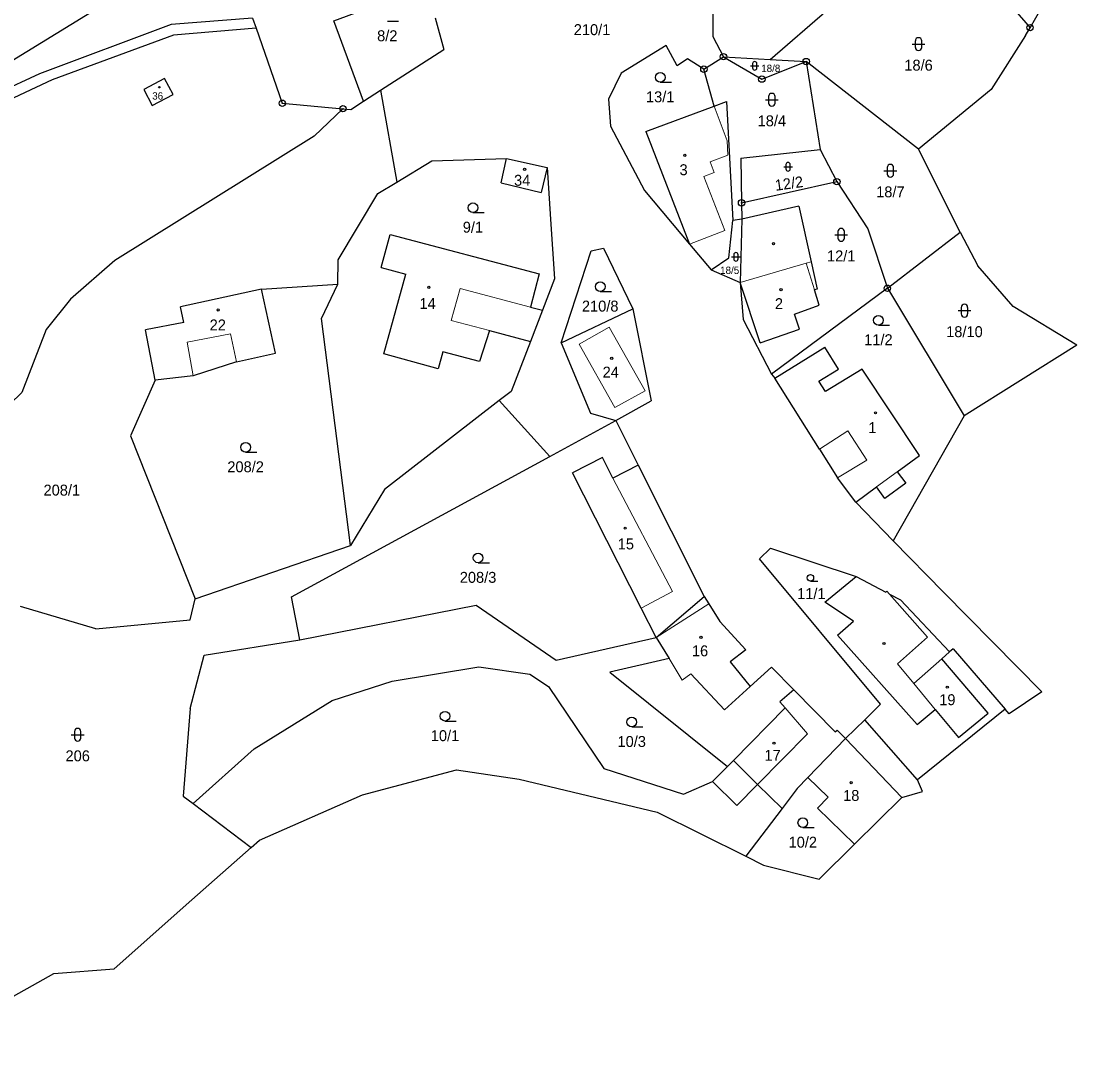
# Model space of a CAD drawing. Extents: x -601877 to -599786, y -1122905 to -1121218.
# Drawn here: x -599979.4 to -599815.2, y -1122397.6 to -1122237.3 of the extents above; entities that cross this region are included whole.
import ezdxf
from ezdxf.enums import TextEntityAlignment as Align

# ---------------------------------------------------------------- set-up
doc = ezdxf.new("R2010")
doc.units = 0
doc.header["$LTSCALE"] = 0.68
for name, color, linetype, lineweight in [('1', 7, 'Continuous', 25), ('3', 7, 'Continuous', 25), ('4', 7, 'Continuous', 13), ('5', 7, 'Continuous', 25), ('8', 7, 'Continuous', 25)]:
    doc.layers.add(name, color=color, linetype=linetype, lineweight=lineweight)
doc.layers.add('2', color=7, linetype='Continuous')

msp = doc.modelspace()

# ---------------------------------------------------------------- linework, layer by layer
at = {"layer": '1'}
for p, q in [((-599832.94, -1122226.2), (-599822.46, -1122238.34)), ((-600006.61, -1122259.26), (-599955.88, -1122228.15)), ((-599822.46, -1122238.34), (-599817.45, -1122229.46)), ((-599871.81, -1122230.28), (-599871.81, -1122239.72)), ((-599862.87, -1122243.28), (-599854, -1122235.63)), ((-599943.4, -1122236.87), (-599942.86, -1122238.42)), ((-599914.97, -1122236.8), (-599913.64, -1122241.71)), ((-599942.86, -1122238.42), (-599955.7, -1122239.53)), ((-599942.86, -1122238.42), (-599938.77, -1122250.1)), ((-599823.14, -1122239.56), (-599822.46, -1122238.34)), ((-599955.7, -1122239.53), (-599974.57, -1122246.46)), ((-599871.81, -1122239.72), (-599870.14, -1122242.85)), ((-599823.14, -1122239.56), (-599828.49, -1122247.93)), ((-599923.49, -1122248.07), (-599913.64, -1122241.71)), ((-599879.04, -1122241.11), (-599886.04, -1122245.39)), ((-599877.33, -1122244.28), (-599879.04, -1122241.11)), ((-599875.74, -1122243.19), (-599877.33, -1122244.28)), ((-599873.19, -1122244.79), (-599875.74, -1122243.19)), ((-599873.19, -1122244.79), (-599870.14, -1122242.85)), ((-599870.14, -1122242.85), (-599862.87, -1122243.28)), ((-599870.14, -1122242.85), (-599864.18, -1122246.34)), ((-599864.18, -1122246.34), (-599857.27, -1122243.61)), ((-599862.87, -1122243.28), (-599857.27, -1122243.61)), ((-599839.83, -1122257.22), (-599857.27, -1122243.61)), ((-599857.27, -1122243.61), (-599855.12, -1122257.3)), ((-599976.54, -1122245.54), (-600006.61, -1122259.26)), ((-599886.04, -1122245.39), (-599888.03, -1122249.47)), ((-599871.6, -1122250.53), (-599873.19, -1122244.79)), ((-599974.57, -1122246.46), (-600009.65, -1122262.88)), ((-599957.1, -1122246.26), (-599960.33, -1122247.96)), ((-599955.77, -1122248.75), (-599957.1, -1122246.26)), ((-599960.33, -1122247.96), (-599958.99, -1122250.44)), ((-599958.99, -1122250.44), (-599955.77, -1122248.75)), ((-599926.15, -1122249.79), (-599923.49, -1122248.07)), ((-599923.49, -1122248.07), (-599920.98, -1122262.38)), ((-599828.49, -1122247.93), (-599839.83, -1122257.22)), ((-599938.77, -1122250.1), (-599929.33, -1122250.94)), ((-599928.09, -1122251.05), (-599926.15, -1122249.79)), ((-599888.03, -1122249.47), (-599887.7, -1122253.66)), ((-599882.23, -1122254.5), (-599871.6, -1122250.53)), ((-599871.6, -1122250.53), (-599869.68, -1122249.81)), ((-599869.68, -1122249.81), (-599868.68, -1122268.34)), ((-599929.33, -1122250.94), (-599933.84, -1122255.22)), ((-599929.33, -1122250.94), (-599928.09, -1122251.05)), ((-599887.7, -1122253.66), (-599882.41, -1122263.69)), ((-599933.84, -1122255.22), (-599964.82, -1122274.55)), ((-599882.23, -1122254.5), (-599875.42, -1122272.02)), ((-599867.45, -1122258.61), (-599855.12, -1122257.3)), ((-599855.12, -1122257.3), (-599852.5, -1122262.29)), ((-599833.33, -1122270.16), (-599839.83, -1122257.22)), ((-599920.98, -1122262.38), (-599915.49, -1122259.04)), ((-599915.49, -1122259.04), (-599903.9, -1122258.67)), ((-599904.75, -1122262.46), (-599903.9, -1122258.67)), ((-599903.9, -1122258.67), (-599897.58, -1122260.09)), ((-599867.45, -1122258.61), (-599867.33, -1122265.58)), ((-599897.58, -1122260.09), (-599898.52, -1122263.97)), ((-599897.58, -1122260.09), (-599897.06, -1122268.12)), ((-599923.9, -1122264.15), (-599920.98, -1122262.38)), ((-599867.33, -1122265.58), (-599852.5, -1122262.29)), ((-599852.5, -1122262.29), (-599847.69, -1122269.61)), ((-599904.75, -1122262.46), (-599898.52, -1122263.97)), ((-599882.41, -1122263.69), (-599875.42, -1122272.02)), ((-599930.06, -1122274.45), (-599923.9, -1122264.15)), ((-599867.33, -1122265.58), (-599867.28, -1122268.11)), ((-599858.4, -1122266.12), (-599867.28, -1122268.11)), ((-599858.4, -1122266.12), (-599856.5, -1122274.74)), ((-599897.06, -1122268.12), (-599896.41, -1122277.42)), ((-599869.29, -1122274.16), (-599868.68, -1122268.34)), ((-599867.28, -1122268.11), (-599868.68, -1122268.34)), ((-599867.28, -1122268.11), (-599867.57, -1122277.97)), ((-599923.38, -1122275.66), (-599922.01, -1122270.51)), ((-599922.01, -1122270.51), (-599898.81, -1122276.65)), ((-599847.69, -1122269.61), (-599844.65, -1122278.87)), ((-599844.65, -1122278.87), (-599833.33, -1122270.16)), ((-599833.33, -1122270.16), (-599830.6, -1122275.4)), ((-599875.42, -1122272.02), (-599872.06, -1122276.02)), ((-599895.37, -1122287.38), (-599890.72, -1122273.05)), ((-599890.72, -1122273.05), (-599888.82, -1122272.61)), ((-599888.82, -1122272.61), (-599884.26, -1122282.07)), ((-599964.82, -1122274.55), (-599971.74, -1122280.57)), ((-599930.12, -1122278.24), (-599930.06, -1122274.45)), ((-599872.06, -1122276.02), (-599869.29, -1122274.16)), ((-599856.5, -1122274.74), (-599855.56, -1122278.99)), ((-599825.09, -1122281.69), (-599830.6, -1122275.4)), ((-599923.38, -1122275.66), (-599919.58, -1122276.67)), ((-599922.98, -1122289.07), (-599919.58, -1122276.67)), ((-599898.81, -1122276.65), (-599900.15, -1122281.81)), ((-599872.06, -1122276.02), (-599867.57, -1122277.97)), ((-599942.01, -1122279), (-599930.12, -1122278.24)), ((-599932.65, -1122283.56), (-599930.12, -1122278.24)), ((-599896.41, -1122277.42), (-599898.29, -1122282.3)), ((-599867.57, -1122277.97), (-599867.06, -1122283.73)), ((-599864.42, -1122287.34), (-599867.57, -1122277.97)), ((-599942.01, -1122279), (-599954.61, -1122281.78)), ((-599939.82, -1122288.96), (-599942.01, -1122279)), ((-599844.65, -1122278.87), (-599862.67, -1122292.24)), ((-599855.56, -1122278.99), (-599855.99, -1122279.13)), ((-599855.26, -1122281.49), (-599855.99, -1122279.13)), ((-599844.65, -1122278.87), (-599832.7, -1122298.69)), ((-599971.74, -1122280.57), (-599975.48, -1122285.31)), ((-599954.08, -1122284.19), (-599954.61, -1122281.78)), ((-599900.15, -1122281.81), (-599898.29, -1122282.3)), ((-599895.37, -1122287.38), (-599884.26, -1122282.07)), ((-599884.26, -1122282.07), (-599881.41, -1122296.36)), ((-599859.08, -1122282.88), (-599855.26, -1122281.49)), ((-599815.17, -1122287.72), (-599825.09, -1122281.69)), ((-599928.14, -1122318.86), (-599932.65, -1122283.56)), ((-599898.29, -1122282.3), (-599900.16, -1122287.14)), ((-599867.06, -1122283.73), (-599862.67, -1122292.24)), ((-599858.3, -1122285.22), (-599859.08, -1122282.88)), ((-599975.48, -1122285.31), (-599979.3, -1122295.06)), ((-599954.08, -1122284.19), (-599960.06, -1122285.32)), ((-599958.57, -1122293.18), (-599960.06, -1122285.32)), ((-599864.42, -1122287.34), (-599858.3, -1122285.22)), ((-599906.54, -1122285.45), (-599908.1, -1122290.27)), ((-599906.54, -1122285.45), (-599900.16, -1122287.14)), ((-599900.16, -1122287.14), (-599903.17, -1122294.92)), ((-599895.37, -1122287.38), (-599890.83, -1122298.29)), ((-599862.17, -1122292.86), (-599854.37, -1122288.03)), ((-599852.26, -1122291.43), (-599854.37, -1122288.03)), ((-599815.17, -1122287.72), (-599832.7, -1122298.69)), ((-599945.87, -1122290.3), (-599952.62, -1122292.47)), ((-599945.87, -1122290.3), (-599939.82, -1122288.96)), ((-599914.54, -1122291.39), (-599922.98, -1122289.07)), ((-599913.82, -1122288.75), (-599914.54, -1122291.39)), ((-599908.1, -1122290.27), (-599913.82, -1122288.75)), ((-599855.3, -1122293.31), (-599852.26, -1122291.43)), ((-599848.55, -1122291.45), (-599854.29, -1122294.94)), ((-599839.64, -1122304.86), (-599848.55, -1122291.45)), ((-599958.57, -1122293.18), (-599962.41, -1122301.83)), ((-599952.62, -1122292.47), (-599958.57, -1122293.18)), ((-599862.67, -1122292.24), (-599862.17, -1122292.86)), ((-599855.22, -1122303.89), (-599862.17, -1122292.86)), ((-599854.29, -1122294.94), (-599855.3, -1122293.31)), ((-599979.3, -1122295.06), (-600015.75, -1122330.35)), ((-599903.17, -1122294.92), (-599905.02, -1122296.35)), ((-599905.02, -1122296.35), (-599922.86, -1122310.16)), ((-599905.02, -1122296.35), (-599897.16, -1122305.05)), ((-599886.87, -1122299.46), (-599881.41, -1122296.36)), ((-599890.83, -1122298.29), (-599886.87, -1122299.46)), ((-599897.16, -1122305.05), (-599886.87, -1122299.46)), ((-599886.87, -1122299.46), (-599883.39, -1122306.4)), ((-599832.7, -1122298.69), (-599843.76, -1122318.16)), ((-599962.41, -1122301.83), (-599952.34, -1122327.15)), ((-599937.33, -1122326.87), (-599897.16, -1122305.05)), ((-599855.22, -1122303.89), (-599852.39, -1122308.35)), ((-599843.11, -1122307.41), (-599839.64, -1122304.86)), ((-599888.96, -1122305.2), (-599893.65, -1122307.59)), ((-599887.33, -1122308.41), (-599888.96, -1122305.2)), ((-599883.39, -1122306.4), (-599887.33, -1122308.41)), ((-599883.39, -1122306.4), (-599873.15, -1122326.79)), ((-599882.94, -1122328.61), (-599893.65, -1122307.59)), ((-599849.56, -1122312.14), (-599852.39, -1122308.35)), ((-599843.11, -1122307.41), (-599841.8, -1122309.18)), ((-599849.56, -1122312.14), (-599846.33, -1122309.78)), ((-599845.02, -1122311.55), (-599846.33, -1122309.78)), ((-599841.8, -1122309.18), (-599845.02, -1122311.55)), ((-599922.86, -1122310.16), (-599928.14, -1122318.86)), ((-599843.76, -1122318.16), (-599849.56, -1122312.14)), ((-599843.76, -1122318.16), (-599835.94, -1122326.14)), ((-599952.34, -1122327.15), (-599928.14, -1122318.86)), ((-599864.54, -1122320.95), (-599862.82, -1122319.31)), ((-599862.82, -1122319.31), (-599849.51, -1122323.71)), ((-599845.71, -1122343.58), (-599864.54, -1122320.95)), ((-599849.51, -1122323.71), (-599844.91, -1122326.14)), ((-599844.91, -1122326.14), (-599844.74, -1122325.99)), ((-599844.74, -1122325.99), (-599844.34, -1122326.44)), ((-599844.34, -1122326.44), (-599842.61, -1122327.35)), ((-599820.64, -1122341.66), (-599835.94, -1122326.14)), ((-599953.11, -1122330.45), (-599952.34, -1122327.15)), ((-599936.06, -1122333.53), (-599937.33, -1122326.87)), ((-599880.59, -1122333.21), (-599873.15, -1122326.79)), ((-599873.15, -1122326.79), (-599872.43, -1122327.95)), ((-599872.43, -1122327.95), (-599870.73, -1122330.69)), ((-599842.61, -1122327.35), (-599834.96, -1122335.44)), ((-599967.79, -1122331.82), (-599979.5, -1122328.38)), ((-599936.06, -1122333.53), (-599908.62, -1122328.14)), ((-599908.62, -1122328.14), (-599896.19, -1122336.72)), ((-599880.59, -1122333.21), (-599882.94, -1122328.61)), ((-599967.79, -1122331.82), (-599953.11, -1122330.45)), ((-599870.73, -1122330.69), (-599866.66, -1122335.1)), ((-599852.4, -1122332.81), (-599849.94, -1122330.64)), ((-599840.03, -1122346.72), (-599852.4, -1122332.81)), ((-599950.91, -1122335.95), (-599936.06, -1122333.53)), ((-599896.19, -1122336.72), (-599880.59, -1122333.21)), ((-599880.59, -1122333.21), (-599878.61, -1122336.46)), ((-599953.11, -1122344.21), (-599950.91, -1122335.95)), ((-599866.66, -1122335.1), (-599869.08, -1122336.97)), ((-599834.96, -1122335.44), (-599836.18, -1122336.53)), ((-599834.42, -1122334.95), (-599834.96, -1122335.44)), ((-599834.42, -1122334.95), (-599826.35, -1122344.32)), ((-599921.68, -1122339.97), (-599908.18, -1122337.77)), ((-599908.18, -1122337.77), (-599900.29, -1122338.89)), ((-599878.61, -1122336.46), (-599887.8, -1122338.59)), ((-599869.08, -1122336.97), (-599865.98, -1122340.82)), ((-599865.98, -1122340.82), (-599862.68, -1122337.8)), ((-599862.68, -1122337.8), (-599859.21, -1122341.33)), ((-599828.97, -1122344.95), (-599836.18, -1122336.53)), ((-599900.29, -1122338.89), (-599897.35, -1122340.82)), ((-599887.8, -1122338.59), (-599869.53, -1122353.24)), ((-599931, -1122342.99), (-599921.68, -1122339.97)), ((-599897.35, -1122340.82), (-599888.77, -1122353.59)), ((-599859.21, -1122341.33), (-599861.37, -1122343.21)), ((-599859.21, -1122341.33), (-599852.77, -1122347.88)), ((-599820.64, -1122341.66), (-599825.71, -1122345.07)), ((-599953.11, -1122344.21), (-599954.21, -1122357.85)), ((-599943.16, -1122350.48), (-599931, -1122342.99)), ((-599868.61, -1122352.31), (-599860.57, -1122344.13)), ((-599861.37, -1122343.21), (-599860.57, -1122344.13)), ((-599848.18, -1122346), (-599845.71, -1122343.58)), ((-599840.03, -1122346.72), (-599837.21, -1122344.37)), ((-599826.35, -1122344.32), (-599839.97, -1122355.34)), ((-599837.21, -1122344.37), (-599833.56, -1122348.76)), ((-599825.71, -1122345.07), (-599826.35, -1122344.32)), ((-599851.15, -1122348.92), (-599848.18, -1122346)), ((-599839.97, -1122355.34), (-599848.18, -1122346)), ((-599833.56, -1122348.76), (-599828.97, -1122344.95)), ((-599852.77, -1122347.88), (-599852.47, -1122347.58)), ((-599852.47, -1122347.58), (-599851.15, -1122348.92)), ((-599851.15, -1122348.92), (-599857.01, -1122354.96)), ((-599952.65, -1122359.03), (-599943.16, -1122350.48)), ((-599869.53, -1122353.24), (-599868.61, -1122352.31)), ((-599926.3, -1122357.66), (-599911.66, -1122353.79)), ((-599911.66, -1122353.79), (-599901.93, -1122355.22)), ((-599888.77, -1122353.59), (-599876.34, -1122357.55)), ((-599871.85, -1122355.59), (-599869.53, -1122353.24)), ((-599901.93, -1122355.22), (-599880.45, -1122360.33)), ((-599876.34, -1122357.55), (-599871.85, -1122355.59)), ((-599871.85, -1122355.59), (-599868.07, -1122359.32)), ((-599857.01, -1122354.96), (-599858.67, -1122356.68)), ((-599857.01, -1122354.96), (-599853.85, -1122358.03)), ((-599839.21, -1122357.13), (-599839.97, -1122355.34)), ((-599942.31, -1122364.71), (-599926.3, -1122357.66)), ((-599864.84, -1122356.04), (-599868.07, -1122359.32)), ((-599861.04, -1122359.8), (-599864.84, -1122356.04)), ((-599858.67, -1122356.68), (-599861.04, -1122359.8)), ((-599842.42, -1122358.05), (-599839.21, -1122357.13)), ((-599954.21, -1122357.85), (-599952.65, -1122359.03)), ((-599952.65, -1122359.03), (-599943.61, -1122365.85)), ((-599853.85, -1122358.03), (-599855.51, -1122359.74)), ((-599849.76, -1122365.32), (-599842.42, -1122358.05)), ((-599880.45, -1122360.33), (-599866.67, -1122367.22)), ((-599861.04, -1122359.8), (-599866.67, -1122367.22)), ((-599849.76, -1122365.32), (-599855.51, -1122359.74)), ((-599952.82, -1122373.99), (-599943.61, -1122365.85)), ((-599943.61, -1122365.85), (-599942.31, -1122364.71)), ((-599855.25, -1122370.79), (-599849.76, -1122365.32)), ((-599866.67, -1122367.22), (-599863.91, -1122368.6)), ((-599863.91, -1122368.6), (-599855.25, -1122370.79)), ((-599964.95, -1122384.7), (-599952.82, -1122373.99)), ((-599996.04, -1122397.64), (-599974.31, -1122385.44)), ((-599974.31, -1122385.44), (-599964.95, -1122384.7))]:
    msp.add_line(p, q, dxfattribs=at)
for points in [[(-599926.15, -1122249.79), (-599930.73, -1122237.29), (-599916.31, -1122231.86)], [(-599943.4, -1122236.87), (-599956.08, -1122237.84), (-599976.54, -1122245.54)], [(-599849.94, -1122330.64), (-599854.4, -1122327.67), (-599849.51, -1122323.71)]]:
    msp.add_lwpolyline(points, dxfattribs=at)
at = {"layer": '3'}
for p, q in [((-599922.433, -1122237.32), (-599920.683, -1122237.32)), ((-599840.801, -1122240.901), (-599838.799, -1122240.901)), ((-599840.301, -1122240.401), (-599840.301, -1122241.402)), ((-599839.299, -1122241.402), (-599839.299, -1122240.401)), ((-599865.961, -1122244.271), (-599864.619, -1122244.271)), ((-599865.625, -1122243.935), (-599865.625, -1122244.606)), ((-599864.955, -1122244.606), (-599864.955, -1122243.935)), ((-599879.983, -1122246.82), (-599878.233, -1122246.82)), ((-599863.121, -1122249.061), (-599863.121, -1122250.062)), ((-599862.119, -1122250.062), (-599862.119, -1122249.061)), ((-599863.621, -1122249.561), (-599861.619, -1122249.561)), ((-599860.771, -1122259.971), (-599859.429, -1122259.971)), ((-599860.435, -1122259.635), (-599860.435, -1122260.306)), ((-599859.765, -1122260.306), (-599859.765, -1122259.635)), ((-599845.181, -1122260.601), (-599843.179, -1122260.601)), ((-599844.681, -1122260.101), (-599844.681, -1122261.102)), ((-599843.679, -1122261.102), (-599843.679, -1122260.101)), ((-599909.113, -1122267.1), (-599907.363, -1122267.1)), ((-599852.831, -1122270.561), (-599850.829, -1122270.561)), ((-599852.331, -1122270.061), (-599852.331, -1122271.062)), ((-599851.329, -1122271.062), (-599851.329, -1122270.061)), ((-599868.545, -1122273.645), (-599868.545, -1122274.316)), ((-599867.875, -1122274.316), (-599867.875, -1122273.645)), ((-599868.881, -1122273.981), (-599867.539, -1122273.981)), ((-599889.313, -1122279.37), (-599887.563, -1122279.37)), ((-599833.161, -1122281.851), (-599833.161, -1122282.852)), ((-599832.159, -1122282.852), (-599832.159, -1122281.851)), ((-599833.661, -1122282.351), (-599831.659, -1122282.351)), ((-599846.043, -1122284.6), (-599844.293, -1122284.6)), ((-599944.473, -1122304.36), (-599942.723, -1122304.36)), ((-599908.313, -1122321.56), (-599906.563, -1122321.56)), ((-599856.625, -1122324.41), (-599855.453, -1122324.41)), ((-599913.453, -1122346.18), (-599911.703, -1122346.18)), ((-599884.413, -1122347.09), (-599882.663, -1122347.09)), ((-599971.601, -1122348.321), (-599969.599, -1122348.321)), ((-599971.101, -1122347.821), (-599971.101, -1122348.822)), ((-599970.099, -1122348.822), (-599970.099, -1122347.821)), ((-599857.803, -1122362.75), (-599856.053, -1122362.75))]:
    msp.add_line(p, q, dxfattribs=at)
for centre, radius in [((-599879.9829, -1122246.0698), 0.75), ((-599909.1129, -1122266.3498), 0.75), ((-599889.3129, -1122278.6198), 0.75), ((-599846.0429, -1122283.8498), 0.75), ((-599944.4729, -1122303.6098), 0.75), ((-599908.3129, -1122320.8098), 0.75), ((-599856.6252, -1122323.9074), 0.5025), ((-599913.4529, -1122345.4298), 0.75), ((-599884.4129, -1122346.3398), 0.75), ((-599857.8029, -1122361.9998), 0.75)]:
    msp.add_circle(centre, radius, dxfattribs=at)
for centre, radius, start, end in [((-599839.8, -1122240.4009), 0.5, 0, 180), ((-599839.8, -1122241.4009), 0.5, 180, 359.98789), ((-599865.29, -1122243.9356), 0.335, 0, 180), ((-599865.29, -1122244.6056), 0.335, 180, 359.98789), ((-599862.62, -1122249.0609), 0.5, 0, 180), ((-599862.62, -1122250.0609), 0.5, 180, 359.98789), ((-599860.1, -1122259.6356), 0.335, 0, 180), ((-599860.1, -1122260.3056), 0.335, 180, 359.98789), ((-599844.18, -1122260.1009), 0.5, 0, 180), ((-599844.18, -1122261.1009), 0.5, 180, 359.98789), ((-599851.83, -1122270.0609), 0.5, 0, 180), ((-599851.83, -1122271.0609), 0.5, 180, 359.98789), ((-599868.21, -1122273.6456), 0.335, 0, 180), ((-599868.21, -1122274.3156), 0.335, 180, 359.98789), ((-599832.66, -1122281.8509), 0.5, 0, 180), ((-599832.66, -1122282.8509), 0.5, 180, 359.98789), ((-599970.6, -1122347.8209), 0.5, 0, 180), ((-599970.6, -1122348.8209), 0.5, 180, 359.98789)]:
    msp.add_arc(centre, radius, start, end, dxfattribs=at)
at = {"layer": '4'}
for p, q in [((-599875.42, -1122272.02), (-599869.95, -1122269.91)), ((-599867.57, -1122277.97), (-599857.27, -1122274.96)), ((-599911.11, -1122278.91), (-599912.48, -1122283.88)), ((-599911.11, -1122278.91), (-599900.15, -1122281.81)), ((-599912.48, -1122283.88), (-599906.54, -1122285.45)), ((-599892.61, -1122287.57), (-599887.9, -1122284.92)), ((-599882.35, -1122294.82), (-599887.9, -1122284.92)), ((-599946.82, -1122285.97), (-599953.59, -1122287.25)), ((-599946.82, -1122285.97), (-599945.87, -1122290.3)), ((-599953.59, -1122287.25), (-599952.62, -1122292.47)), ((-599887.07, -1122297.42), (-599892.61, -1122287.57)), ((-599887.07, -1122297.42), (-599882.35, -1122294.82)), ((-599855.22, -1122303.89), (-599850.78, -1122301.06)), ((-599847.87, -1122305.63), (-599850.78, -1122301.06)), ((-599852.39, -1122308.35), (-599847.87, -1122305.63)), ((-599846.33, -1122309.78), (-599843.11, -1122307.41)), ((-599878.05, -1122326.05), (-599887.33, -1122308.41)), ((-599882.94, -1122328.61), (-599878.05, -1122326.05)), ((-599844.34, -1122326.44), (-599838.39, -1122333.13)), ((-599880.59, -1122333.21), (-599872.43, -1122327.95)), ((-599843.08, -1122337.3), (-599838.39, -1122333.13)), ((-599878.61, -1122336.46), (-599876.56, -1122339.83)), ((-599843.08, -1122337.3), (-599840.55, -1122340.35)), ((-599840.55, -1122340.35), (-599836.18, -1122336.53)), ((-599876.56, -1122339.83), (-599875.24, -1122338.84)), ((-599875.24, -1122338.84), (-599869.96, -1122344.45)), ((-599869.96, -1122344.45), (-599865.98, -1122340.82)), ((-599840.55, -1122340.35), (-599837.21, -1122344.37)), ((-599842.42, -1122358.05), (-599851.15, -1122348.92)), ((-599864.84, -1122356.04), (-599868.61, -1122352.31))]:
    msp.add_line(p, q, dxfattribs=at)
for points in [[(-599869.45, -1122258.17), (-599869.59, -1122255.92), (-599871.6, -1122250.53)], [(-599869.45, -1122258.17), (-599872.22, -1122259.23), (-599871.58, -1122260.89), (-599873.18, -1122261.51), (-599869.95, -1122269.91)], [(-599855.99, -1122279.13), (-599857.27, -1122274.96), (-599856.5, -1122274.74)], [(-599860.57, -1122344.13), (-599857.06, -1122348.16), (-599864.84, -1122356.04)]]:
    msp.add_lwpolyline(points, dxfattribs=at)
at = {"layer": '5'}
for centre, radius in [((-599957.8946, -1122247.5994), 0.1172), ((-599876.1568, -1122258.1992), 0.175), ((-599901.0868, -1122260.3592), 0.175), ((-599862.3668, -1122271.9292), 0.175), ((-599915.9768, -1122278.7392), 0.175), ((-599861.1868, -1122279.0992), 0.175), ((-599948.7468, -1122282.2392), 0.175), ((-599887.5268, -1122289.7592), 0.175), ((-599846.4968, -1122298.2492), 0.175), ((-599885.4368, -1122316.1792), 0.175), ((-599873.6568, -1122333.1492), 0.175), ((-599845.1868, -1122334.1192), 0.175), ((-599835.3268, -1122340.9192), 0.175), ((-599862.2968, -1122349.6292), 0.175), ((-599850.2768, -1122355.7592), 0.175)]:
    msp.add_circle(centre, radius, dxfattribs=at)
at = {"layer": '8'}
for centre, radius in [((-599822.46, -1122238.3399), 0.5), ((-599822.46, -1122238.3399), 0.0303), ((-599870.14, -1122242.8499), 0.5), ((-599873.19, -1122244.7899), 0.5), ((-599870.14, -1122242.8499), 0.0303), ((-599857.27, -1122243.6099), 0.5), ((-599857.27, -1122243.6099), 0.0303), ((-599873.19, -1122244.7899), 0.0303), ((-599864.18, -1122246.3399), 0.5), ((-599864.18, -1122246.3399), 0.0303), ((-599938.77, -1122250.0999), 0.5), ((-599938.77, -1122250.0999), 0.0303), ((-599929.33, -1122250.9399), 0.5), ((-599929.33, -1122250.9399), 0.0303), ((-599852.5, -1122262.2899), 0.5), ((-599852.5, -1122262.2899), 0.0303), ((-599867.33, -1122265.5799), 0.5), ((-599867.33, -1122265.5799), 0.0303), ((-599844.65, -1122278.8699), 0.5), ((-599844.65, -1122278.8699), 0.0303)]:
    msp.add_circle(centre, radius, dxfattribs=at)

# ---------------------------------------------------------------- texts
at = {"layer": '2'}
for s, height, p in [('210/1', 1.7, (-599890.59, -1122239.495)), ('8/2', 1.7, (-599922.44, -1122240.445)), ('18/8', 1.14, (-599862.79, -1122245.235)), ('18/6', 1.7, (-599839.799, -1122245.025)), ('36', 1.14, (-599958.16, -1122249.525)), ('13/1', 1.7, (-599879.989, -1122249.945)), ('18/4', 1.7, (-599862.619, -1122253.685)), ('3', 1.7, (-599876.35, -1122261.285)), ('34', 1.7, (-599901.459, -1122262.925)), ('18/7', 1.7, (-599844.179, -1122264.725)), ('9/1', 1.7, (-599909.12, -1122270.225)), ('12/1', 1.7, (-599851.829, -1122274.685)), ('18/5', 1.14, (-599869.18, -1122276.645)), ('14', 1.7, (-599916.169, -1122282.095)), ('2', 1.7, (-599861.51, -1122282.115)), ('210/8', 1.7, (-599889.32, -1122282.495)), ('22', 1.7, (-599948.809, -1122285.425)), ('18/10', 1.7, (-599832.66, -1122286.475)), ('11/2', 1.7, (-599846.049, -1122287.725)), ('24', 1.7, (-599887.679, -1122292.765)), ('1', 1.7, (-599846.98, -1122301.395)), ('208/2', 1.7, (-599944.48, -1122307.485)), ('208/1', 1.7, (-599973.07, -1122311.115)), ('15', 1.7, (-599885.329, -1122319.485)), ('208/3', 1.7, (-599908.32, -1122324.685)), ('11/1', 1.7, (-599856.479, -1122327.215)), ('16', 1.7, (-599873.789, -1122336.115)), ('19', 1.7, (-599835.319, -1122343.715)), ('10/1', 1.7, (-599913.459, -1122349.305)), ('10/3', 1.7, (-599884.419, -1122350.215)), ('206', 1.7, (-599970.599, -1122352.445)), ('17', 1.7, (-599862.509, -1122352.365)), ('18', 1.7, (-599850.269, -1122358.605)), ('10/2', 1.7, (-599857.809, -1122365.875))]:
    msp.add_text(s, height=height, dxfattribs=at).set_placement(p, align=Align.CENTER)
msp.add_text('12/2', height=1.7, rotation=8, dxfattribs=at).set_placement((-599859.8308, -1122263.4116), align=Align.CENTER)

doc.saveas('drawing.dxf')
